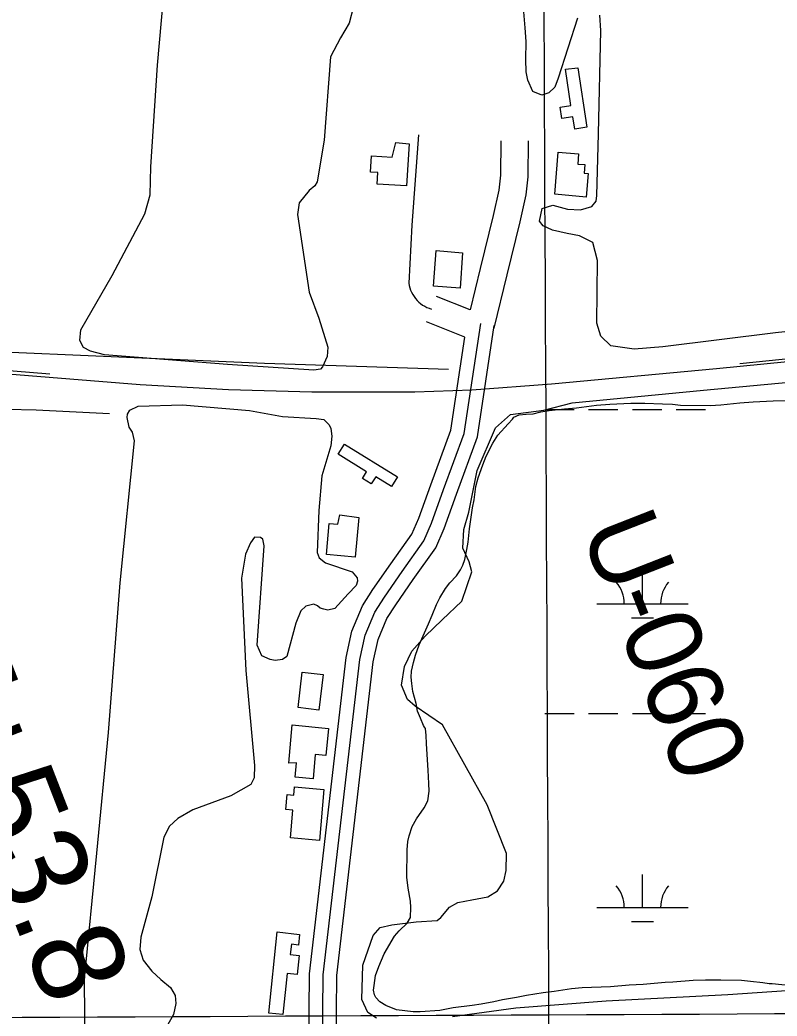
# Model space of a CAD drawing. Extents: x 3445503 to 3483459, y 540493 to 566012.
# Drawn here: x 3454317 to 3455146, y 551970 to 553061 of the extents above; entities that cross this region are included whole.
import ezdxf

# ---------------------------------------------------------------- set-up
doc = ezdxf.new("R2010")
doc.units = 0
for name, color, linetype in [('V-BLDG-OTLN', 7, 'Continuous'), ('V-GRID-MAJR', 7, 'Continuous'), ('V-RAIL-TRAK', 7, 'Continuous'), ('V-RIVR-RANG-IDEN', 7, 'Continuous'), ('V-ROAD-CNTR', 7, 'Continuous'), ('V-SITE-VEGE', 7, 'Continuous'), ('V-SURV-IDEN', 7, 'Continuous'), ('V-TOPO-SHOR', 7, 'Continuous'), ('V-WETL-SWMP', 7, 'Continuous')]:
    doc.layers.add(name, color=color, linetype=linetype)

msp = doc.modelspace()

# ---------------------------------------------------------------- linework, layer by layer
at = {"layer": 'V-BLDG-OTLN'}
for points in [[(3454927.924, 553008.307), (3454937.5500000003, 552943.345), (3454924.357, 552941.389), (3454922.393, 552954.648), (3454910.377, 552952.868), (3454908.536, 552965.289), (3454920.0810000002, 552966.9990000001), (3454914.17, 553006.906)], [(3454743.0130000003, 552925.144), (3454740.268, 552879.019), (3454707.863, 552880.948), (3454708.623, 552893.711), (3454700.75, 552894.182), (3454701.821, 552912.088), (3454724.458, 552910.747), (3454728.482, 552926.602)], [(3454902.474, 552870.12), (3454906.287, 552915.906), (3454928.576, 552914.0480000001), (3454927.66, 552903.079), (3454935.396, 552902.438), (3454934.605, 552892.943), (3454939.164, 552892.564), (3454937.026, 552866.846)], [(3454801.393, 552805.637), (3454798.784, 552767.251), (3454769.798, 552769.2220000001), (3454772.481, 552808.211)], [(3454672.24, 552596.311), (3454730.131, 552560.444), (3454723.612, 552549.922), (3454706.509, 552560.5160000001), (3454701.5840000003, 552552.56), (3454691.921, 552558.519), (3454696.507, 552565.939), (3454665.34, 552585.178)], [(3454688.046, 552516.001), (3454684.057, 552472.397), (3454652.407, 552475.2930000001), (3454655.518, 552509.279), (3454665.105, 552508.407), (3454666.981, 552518.632)], [(3454644.1920000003, 552304.666), (3454621.531, 552307.7440000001), (3454626.039, 552346.586), (3454648.751, 552343.95)], [(3454611.093, 552246.74), (3454615.054, 552288.615), (3454654.582, 552284.88), (3454651.764, 552255.071), (3454640.268, 552256.171), (3454637.803, 552229.701), (3454618.066, 552231.529), (3454619.52, 552247.127)], [(3454649.523, 552217.888), (3454644.674, 552162.045), (3454613.018, 552164.7930000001), (3454615.656, 552195.175), (3454608.021, 552195.841), (3454609.483, 552212.278), (3454616.71, 552211.664), (3454617.523, 552220.812)], [(3454598.614, 552061.826), (3454623.094, 552059.022), (3454621.892, 552047.5430000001), (3454614.073, 552048.36), (3454612.893, 552037.06), (3454622.406, 552036.064), (3454620.221, 552015.193), (3454609.393, 552016.326), (3454604.687, 551971.339), (3454589.316, 551972.949)]]:
    msp.add_lwpolyline(points, close=True, dxfattribs=at)
at = {"layer": 'V-GRID-MAJR'}
for points in [[(3454925.2, 545912.109), (3454896.117, 551971.152), (3454867.026, 558032.129), (3454837.934, 564093.122), (3454837.9250000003, 564095.039)], [(3449621.526, 551946.219), (3454896.117, 551971.152), (3460170.705, 551996.853), (3465445.288, 552023.321), (3470719.8680000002, 552050.556), (3475994.444, 552078.558), (3481269.015, 552107.327), (3481269.0160000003, 552107.327)]]:
    msp.add_spline(points, degree=3, dxfattribs=at)
at = {"layer": 'V-RAIL-TRAK'}
for points in [[(3454811.811, 552655.304), (3454749.165, 552653.172), (3454636.531, 552653.207), (3454545.239, 552655.7710000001), (3454448.5160000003, 552661.335), (3454271.258, 552675.411), (3454052.7630000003, 552693.757), (3453867.4620000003, 552709.262), (3453653.79, 552726.556), (3453517.3710000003, 552737.433), (3453459.687, 552742.3150000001), (3453318.846, 552753.493), (3453114.531, 552770.62), (3452923.7430000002, 552786.2220000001), (3452689.776, 552805.486)], [(3455824.363, 552754.742), (3455629.733, 552735.233), (3455447.365, 552715.509), (3455261.136, 552696.497), (3455079.769, 552678.694), (3454899.066, 552661.845), (3454811.811, 552655.304)]]:
    msp.add_lwpolyline(points, dxfattribs=at)
at = {"layer": 'V-ROAD-CNTR'}
for p, q in [((3454809.708410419, 552743.473284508), (3454773.0876437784, 552758.1026353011)), ((3454804.0793539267, 552713.4167685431), (3454761.9583562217, 552730.243364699))]:
    msp.add_line(p, q, dxfattribs=at)
for points in [[(3462631.285699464, 553461.3070510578), (3461591.307779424, 553353.2252672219), (3460578.969804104, 553249.1104754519), (3460106.5807488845, 553200.928571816), (3459452.7400565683, 553132.438708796), (3458819.349323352, 553067.889837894), (3458004.174953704, 552983.141007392), (3457426.1801096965, 552925.1971232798), (3456974.920012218, 552876.8662199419), (3456477.6580067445, 552824.1753253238), (3455722.188517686, 552747.3734789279), (3455105.053751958, 552684.0966054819)], [(3454349.472263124, 552672.890627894), (3453755.1854517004, 552721.4145308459), (3452720.8545203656, 552805.935361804), (3451507.8359464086, 552903.1211674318), (3450296.1343698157, 553003.1869672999), (3449613.759734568, 553058.9048558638)], [(3454753.355, 552934.981), (3454746.113, 552836.216), (3454742.734, 552772.724)], [(3454843.311620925, 552928.5674820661), (3454842.9682805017, 552890.8343695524), (3454841.200373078, 552874.3143990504), (3454835.0994149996, 552846.6457818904), (3454820.7872991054, 552788.6961687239), (3454809.708410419, 552743.473284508)], [(3454873.3103790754, 552928.2945179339), (3454872.9537194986, 552889.0976304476), (3454870.853626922, 552869.4736009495), (3454864.3145850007, 552839.8182181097), (3454849.918937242, 552781.530385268), (3454835.648287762, 552723.2790617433)], [(3454742.734, 552772.724), (3454743.178, 552770.09), (3454743.826, 552767.4990000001), (3454744.676, 552764.968), (3454745.72, 552762.508), (3454746.953, 552760.1410000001), (3454748.366, 552757.8740000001), (3454749.955, 552755.727), (3454751.7060000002, 552753.71), (3454753.609, 552751.836), (3454755.6550000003, 552750.118), (3454757.826, 552748.563), (3454760.113, 552747.183), (3454762.501, 552745.987), (3454764.975, 552744.982), (3454767.523, 552744.1730000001)], [(3454647.711666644, 551895.8491819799), (3454648.832664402, 552014.969943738), (3454688.914584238, 552360.119253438), (3454694.7965724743, 552386.9081998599), (3454705.329551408, 552412.1651493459), (3454715.892530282, 552428.5721165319), (3454735.2654915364, 552456.6240604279), (3454759.04344398, 552490.221993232), (3454767.606426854, 552509.4989546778), (3454780.7534005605, 552546.599880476), (3454803.331355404, 552607.8477579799), (3454821.5033190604, 552728.371516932)], [(3454662.7106366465, 551895.7081822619), (3454663.824634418, 552014.0319456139), (3454703.7275546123, 552357.6392583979), (3454709.1585437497, 552382.377208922), (3454718.6615247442, 552405.1641633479), (3454728.37350532, 552420.24813318), (3454747.5594669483, 552448.0290776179), (3454772.1474177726, 552482.772008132), (3454781.550398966, 552503.9409657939), (3454794.860372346, 552541.5008906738), (3454817.935326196, 552604.096765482), (3454836.3352893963, 552726.1355214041)], [(3454632.712696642, 551895.9901816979), (3454633.840694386, 552015.9079418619), (3454674.101613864, 552362.599248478), (3454680.4346011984, 552391.4391907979), (3454691.9975780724, 552419.1661353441), (3454703.411555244, 552436.8960998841), (3454722.971516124, 552465.219043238), (3454745.939470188, 552497.6719783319), (3454753.662454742, 552515.056943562), (3454766.646428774, 552551.6988702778), (3454788.727384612, 552611.598750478), (3454804.0793539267, 552713.4167685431)]]:
    msp.add_lwpolyline(points, dxfattribs=at)
at = {"layer": 'V-SITE-VEGE'}
for points in [[(3454682.16, 553075.549), (3454677.309, 553057.191), (3454667.968, 553041.174), (3454656.9250000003, 553020.333), (3454649.8310000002, 552929.201), (3454642.239, 552883.711), (3454639.5700000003, 552879.226), (3454633.6580000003, 552874.153), (3454622.416, 552860.433), (3454620.577, 552847.846), (3454633.651, 552762.836), (3454644.154, 552734.178), (3454653.953, 552702.617), (3454653.128, 552692.276), (3454648.071, 552680.715), (3454645.767, 552678.4890000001), (3454638.628, 552677.3200000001), (3454544.248, 552683.503), (3454409.492, 552693.947), (3454394.031, 552698.103), (3454386.335, 552702.121), (3454382.257, 552709.633), (3454383.4390000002, 552721.587), (3454417.807, 552780.85), (3454453.616, 552848.502), (3454459.481, 552869.432), (3454460.02, 552900.165), (3454467.466, 553011.351), (3454476.703, 553113.769)], [(3454927.318, 553062.741), (3454906.089, 552997.035), (3454902.681, 552987.377), (3454896.09, 552981.014), (3454888.273, 552978.56), (3454878.627, 552982.615), (3454873.0130000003, 552995.022), (3454871.23, 553004.121), (3454870.8200000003, 553017.734), (3454871.16, 553037.164), (3454870.126, 553052.081), (3454868.487, 553069.602)], [(3455280.443, 552732.648), (3455144.146, 552718.1900000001), (3455020.791, 552702.856), (3454989.647, 552700.161), (3454963.7970000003, 552703.854), (3454952.969, 552714.409), (3454948.685, 552728.735), (3454949.24, 552797.398), (3454944.399, 552816.915), (3454929.626, 552824.301), (3454916.073, 552827.129), (3454899.9390000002, 552830.649), (3454889.6580000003, 552835.3640000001), (3454885.861, 552840.613), (3454888.6890000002, 552854.169), (3454900.414, 552857.851), (3454916.538, 552853.681), (3454930.773, 552852.784), (3454943.145, 552856.454), (3454947.782, 552862.205), (3454948.544, 552868.666), (3454950.3680000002, 552936.011), (3454952.998, 553049.337), (3454951.9990000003, 553066.2)], [(3454388.553, 551887.777), (3454387.461, 552010.241), (3454400.855, 552147.961), (3454413.8310000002, 552280.196), (3454426.392, 552444.1), (3454442.362, 552599.866), (3454439.941, 552609.277), (3454436.486, 552614.829), (3454434.086, 552625.534), (3454434.473, 552629.081), (3454437.136, 552633.558), (3454446.259, 552637.92), (3454494.7460000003, 552639.333), (3454568.3000000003, 552633.202), (3454604.365, 552626.433), (3454641.157, 552624.172), (3454649.538, 552623.058), (3454655.256, 552617.465), (3454657.119, 552613.232), (3454658.264, 552604.812), (3454657.437, 552594.488), (3454647.49, 552561.384), (3454644.244, 552523.642), (3454642.144, 552477.478), (3454644.303, 552471.625), (3454651.313, 552466.009), (3454680.5470000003, 552456.453), (3454686.2460000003, 552449.8910000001), (3454686.5, 552446.01), (3454685.13, 552441.511), (3454676.2460000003, 552432.297), (3454661.748, 552416.075), (3454653.961, 552414.273), (3454649.458, 552415.319), (3454645.6040000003, 552416.679), (3454642.736, 552418.991), (3454638.573, 552421.002), (3454629.805, 552418.571), (3454624.548, 552413.4940000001), (3454618.8200000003, 552400.025), (3454609.139, 552363.687), (3454604.232, 552360.22), (3454596.134, 552359.069), (3454590.983, 552360.127), (3454581.685, 552364.166), (3454576.721, 552375.885), (3454584.116, 552484.632), (3454582.632, 552492.088), (3454580.403, 552494.067), (3454573.62, 552494.185), (3454569.316, 552488.121), (3454563.927, 552475.616), (3454559.594, 552449.523), (3454564.286, 552348.317), (3454573.77, 552244.121), (3454573.2090000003, 552230.561), (3454569.531, 552223.518), (3454547.666, 552210.978), (3454506.043, 552195.552), (3454489.724, 552186.1460000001), (3454480.529, 552177.583), (3454474.505, 552165.733), (3454461.085, 552100.384), (3454449.323, 552056.006), (3454448.119, 552042.456), (3454451.789, 552030.762), (3454461.275, 552018.966), (3454471.13, 552009.747), (3454481.643, 552001.162), (3454486.656, 551992.352), (3454487.465, 551983.291), (3454484.997, 551971.38), (3454470.663, 551946.11)], [(3454761.893, 552268.18), (3454761.68, 552277.0380000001), (3454761.096, 552284.839), (3454759.702, 552286.281), (3454758.667, 552288.069), (3454755.6040000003, 552295.91), (3454752.186, 552303.756), (3454750.545, 552311.93), (3454747.211, 552325.09), (3454745.933, 552333.966), (3454745.3370000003, 552341.061), (3454745.4390000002, 552347.432), (3454747.715, 552356.963), (3454749.97, 552365.075), (3454754.045, 552376.346), (3454764.326, 552399.207), (3454768.373, 552408.708), (3454773.167, 552420.677), (3454776.821, 552427.703), (3454783.0100000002, 552438.232), (3454787.708, 552444.179), (3454794.915, 552451.857), (3454799.271, 552458.52), (3454801.833, 552463.791), (3454804.055, 552469.779), (3454806.355, 552480.724), (3454807.545, 552488.852), (3454809.194, 552503.35), (3454812.393, 552526.325), (3454814.301, 552535.15), (3454815.95, 552549.645), (3454818.58, 552559.171), (3454823.767, 552573.611), (3454827.4620000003, 552583.118), (3454834.767, 552597.171), (3454840.221, 552605.941), (3454851.401, 552618.515), (3454856.085, 552623.4), (3454857.541, 552625.858), (3454863.599, 552628.2390000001), (3454871.054, 552629.186), (3454878.85, 552629.419), (3454887.3880000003, 552631.76), (3454896.264, 552633.036), (3454913.298, 552634.8910000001), (3454926.423, 552636.1), (3454948.077, 552638.944), (3454962.974, 552640.126), (3454986.0160000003, 552641.179), (3455001.2430000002, 552640.937), (3455020.361, 552640.28), (3455031.34, 552640.105), (3455040.177, 552638.901), (3455072.759, 552638.385), (3455084.461, 552639.264), (3455105.396, 552641.41), (3455119.9390000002, 552642.596), (3455141.918, 552643.667), (3455155.031, 552644.167)], [(3455176.0130000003, 552001.252), (3455140.65, 552005.002), (3455137.461, 552005.051), (3455130.396, 552006.225), (3455116.957, 552007.503), (3455107.057, 552008.723), (3455084.392, 552009.082), (3455067.741, 552008.992), (3455054.272, 552008.496), (3455031.928, 552006.725), (3455023.423, 552006.505), (3454999.301, 552004.406), (3454984.056, 552003.587), (3454963.482, 552001.789), (3454932.643, 552000.507), (3454920.937, 551999.628), (3454901.765, 551996.743), (3454889.696, 551995.166), (3454871.586, 551992.264), (3454860.566, 551989.96), (3454845.294, 551987.367), (3454835.699, 551985.395), (3454821.84, 551982.779), (3454811.897, 551981.166), (3454791.313, 551978.659), (3454776.741, 551975.702), (3454755.11, 551974.272), (3454747.319, 551974.397), (3454729.287, 551976.453), (3454717.673, 551981.243), (3454711.004, 551985.245), (3454706.474, 551989.9230000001), (3454705.108, 551993.13), (3454704.123, 551998.107), (3454704.557, 552003.059), (3454706.147, 552014.015), (3454709.845, 552023.875), (3454715.737, 552037.95), (3454727.024, 552057.255), (3454732.078, 552063.196), (3454740.713, 552071.56), (3454744.35, 552077.526), (3454744.876, 552088.497), (3454744.6350000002, 552095.587), (3454742.025, 552109.7980000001), (3454740.446, 552121.867), (3454740.917, 552151.6140000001), (3454741.771, 552160.81), (3454742.937, 552167.167), (3454746.285, 552177.389), (3454751.024, 552185.814), (3454759.362, 552197.727), (3454763.38, 552205.456), (3454764.965, 552216.059), (3454764.7460000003, 552224.564), (3454763.912, 552239.101), (3454763.0300000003, 552250.451), (3454761.893, 552268.18)]]:
    msp.add_lwpolyline(points, dxfattribs=at)
at = {"layer": 'V-TOPO-SHOR'}
for points in [[(3454786.28783241, 552677.9547991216), (3454584.4828427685, 552684.6816321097), (3454113.604533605, 552704.862131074), (3453622.5457254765, 552745.2231290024), (3453588.911560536, 552765.4036279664), (3453562.004228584, 552751.9499619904), (3453521.6432306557, 552758.6767949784)], [(3454414.984, 552629.327), (3454334.381, 552633.427), (3454302.1210000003, 552633.99), (3454270.727, 552632.747), (3454217.952, 552639.049), (3454074.748, 552651.417), (3453926.137, 552662.085), (3453800.761, 552668.761), (3453784.63, 552669.044), (3453654.994, 552688.344)]]:
    msp.add_lwpolyline(points, dxfattribs=at)
at = {"layer": 'V-WETL-SWMP'}
for p, q in [((3454893.0236526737, 552633.9926471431), (3454923.651831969, 552633.9926471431)), ((3454939.651830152, 552633.9926471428), (3454971.6518265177, 552633.9926471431)), ((3454987.6518247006, 552633.9926471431), (3455019.651821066, 552633.9926471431)), ((3455035.651819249, 552633.9926471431), (3455067.6518156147, 552633.9926471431)), ((3454998.4958673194, 552421.3886670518), (3454998.4958598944, 552457.388663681)), ((3454948.495872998, 552421.3886670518), (3455048.495861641, 552421.3886670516)), ((3454986.495871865, 552405.9576684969), (3455010.4958691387, 552405.9576684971)), ((3454891.6519042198, 552301.3176782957), (3454923.6519005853, 552301.3176782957)), ((3454939.651898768, 552301.3176782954), (3454971.651895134, 552301.3176782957)), ((3454987.6518933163, 552301.3176782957), (3455019.651889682, 552301.3176782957)), ((3455035.6518878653, 552301.3176782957), (3455067.651884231, 552301.3176782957)), ((3454998.4959359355, 552088.713698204), (3454998.4959285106, 552124.7136948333)), ((3454948.4959416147, 552088.713698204), (3455048.495930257, 552088.7136982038)), ((3454986.4959404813, 552073.2826996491), (3455010.4959377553, 552073.2826996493))]:
    msp.add_line(p, q, dxfattribs=at)
for points in [[(3454707.1350000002, 551967.343), (3454697.886, 551973.637), (3454691.036, 551987.958), (3454692.336, 552025.373), (3454703.559, 552058.0970000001), (3454711.455, 552066.6730000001), (3454724.094, 552069.679), (3454750.613, 552072.765), (3454773.555, 552074.3), (3454777.811, 552077.776), (3454787.366, 552088.905), (3454796.4960000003, 552094.232), (3454811.716, 552097.193), (3454829.201, 552100.437), (3454839.961, 552106.704), (3454846.606, 552117.561), (3454849.39, 552129.131), (3454849.574, 552147.844), (3454828.531, 552201.216), (3454779.643, 552288.687), (3454749.622, 552309.25), (3454741.346, 552316.505), (3454734.5100000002, 552332.138), (3454738.102, 552352.76), (3454746.15, 552369.425), (3454760.661, 552385.977), (3454779.0700000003, 552403.754), (3454800.756, 552424.059), (3454811.661, 552456.188), (3454808.622, 552467.23), (3454801.774, 552482.216), (3454802.782, 552502.883), (3454808.279, 552521.532), (3454817.482, 552567.265), (3454837.693, 552614.0970000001), (3454854.108, 552628.677), (3454890.632, 552633.365), (3454921.77, 552641.537), (3455065.365, 552655.491), (3455229.646, 552670.697)], [(3455231.237, 552002.39), (3455091.969, 551992.885), (3454958.881, 551986.177), (3454859.983, 551978.225), (3454790.428, 551968.791)]]:
    msp.add_lwpolyline(points, dxfattribs=at)
for centre, radius, start, end in [((3454943.252937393, 552421.8634701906), 35.24628790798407, 359.22817992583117, 40.771838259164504), ((3455053.7387970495, 552421.8634701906), 35.24628790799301, 139.22817695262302, 180.77183528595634), ((3454943.2530060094, 552089.1885013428), 35.24628790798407, 359.22817992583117, 40.771838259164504), ((3455053.7388656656, 552089.1885013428), 35.24628790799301, 139.22817695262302, 180.77183528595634)]:
    msp.add_arc(centre, radius, start, end, dxfattribs=at)

# ---------------------------------------------------------------- texts
at = {"layer": 'V-RIVR-RANG-IDEN'}
msp.add_text('U-060', height=82.99999799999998, rotation=291.3712755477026, dxfattribs=at).set_placement((3454929.9573545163, 552502.4867615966))
at = {"layer": 'V-SURV-IDEN'}
msp.add_text('3845+53.8', height=100, rotation=291.1995281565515, dxfattribs=at).set_placement((3454117.867462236, 552569.4222961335))

doc.saveas('drawing.dxf')
